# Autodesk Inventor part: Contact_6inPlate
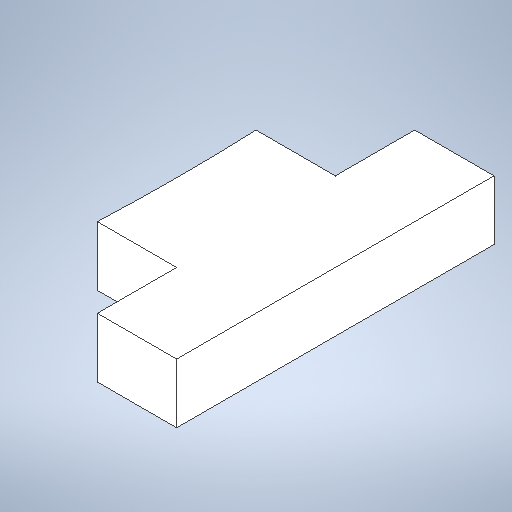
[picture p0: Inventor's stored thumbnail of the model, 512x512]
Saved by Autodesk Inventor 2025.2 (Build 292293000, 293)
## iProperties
Created: 2025-09
Part Number: Contact_6inPlate
Material: Generic
Document SubType Name: Modeling
Designer: tyler
Density: 1 g/cm^3
Appearance: Default
Author: tyler
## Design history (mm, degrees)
sketch "Sketch1"
  geometry: L1 (0, 0)-(0, -12.7); L2 (0, 0)-(0, 12.7); L3 (0, 12.7)-(6.35, 12.7); L4 (0, -12.7)-(6.35, -12.7); L5 (6.35, -12.7)-(6.35, -6.35); L6 (6.35, -12.7)-(12.7, -12.7); L7 (6.35, 12.7)-(6.35, 6.35); L8 (6.35, 6.35)-(12.7, 6.35); L9 (6.35, -6.35)-(12.7, -6.35); A1 r 152.4 centre (164.968, 0) between (12.7, 6.35) and (12.7, -6.35)
  constraints: 18 end point, 5 horizontal, 4 vertical, 2 point on circle, 1 centre point, 1 perpendicular
  dimensions: "d0" = 12.7 distance of L1.start L1.end; "d1" = 12.7 distance of L1.start L2.end; "d2" = 6.35 distance of L2.end L3.end; "d3" = 6.35 distance of L1.end L4.end; "d4" = 6.35 distance of L4.end L5.end; "d5" = 90 deg angle of L6 L5 (derived); "d6" = 6.35 distance of L3.end L7.end; "d7" = 6.35 distance of L7.end L8.end; "d8" = 6.35 distance of L5.end L9.end; "d9" = 152.4 radius of A1
extrude "Extrusion1" new body sketch "Sketch1" distance "d10" = 4.7625; taper "d11" = 0 deg
sketch "Sketch2"
  geometry: L1 (25.4, 0)-(0, 0) reference; L2 (0, 0)-(4.763, 4.763); L3 (25.4, 4.763)-(0, 4.763) reference; L4 (0, 0)-(6.735, 0); L5 (25.4, 0)-(20.638, 4.763); L6 (25.4, 0)-(32.135, 0); C1 r 1.587 at (23.019, 2.381); C2 r 1.588 at (2.381, 2.381); 1 further point
  constraints: 8 end point, 2 centre point, 2 equal length, 2 horizontal, 2 midpoint, 2 point on line
  dimensions: "d12" = 45 deg angle of L4 L2; "d13" = 135 deg angle of L6 L5; "d14" = 3.175 diameter of C1; "d15" = 3.175 diameter of C2
extrude "Extrusion2" cut sketch "Sketch2" distance "d16" = 4.7625; taper "d17" = 0 deg
body "Solid1"
